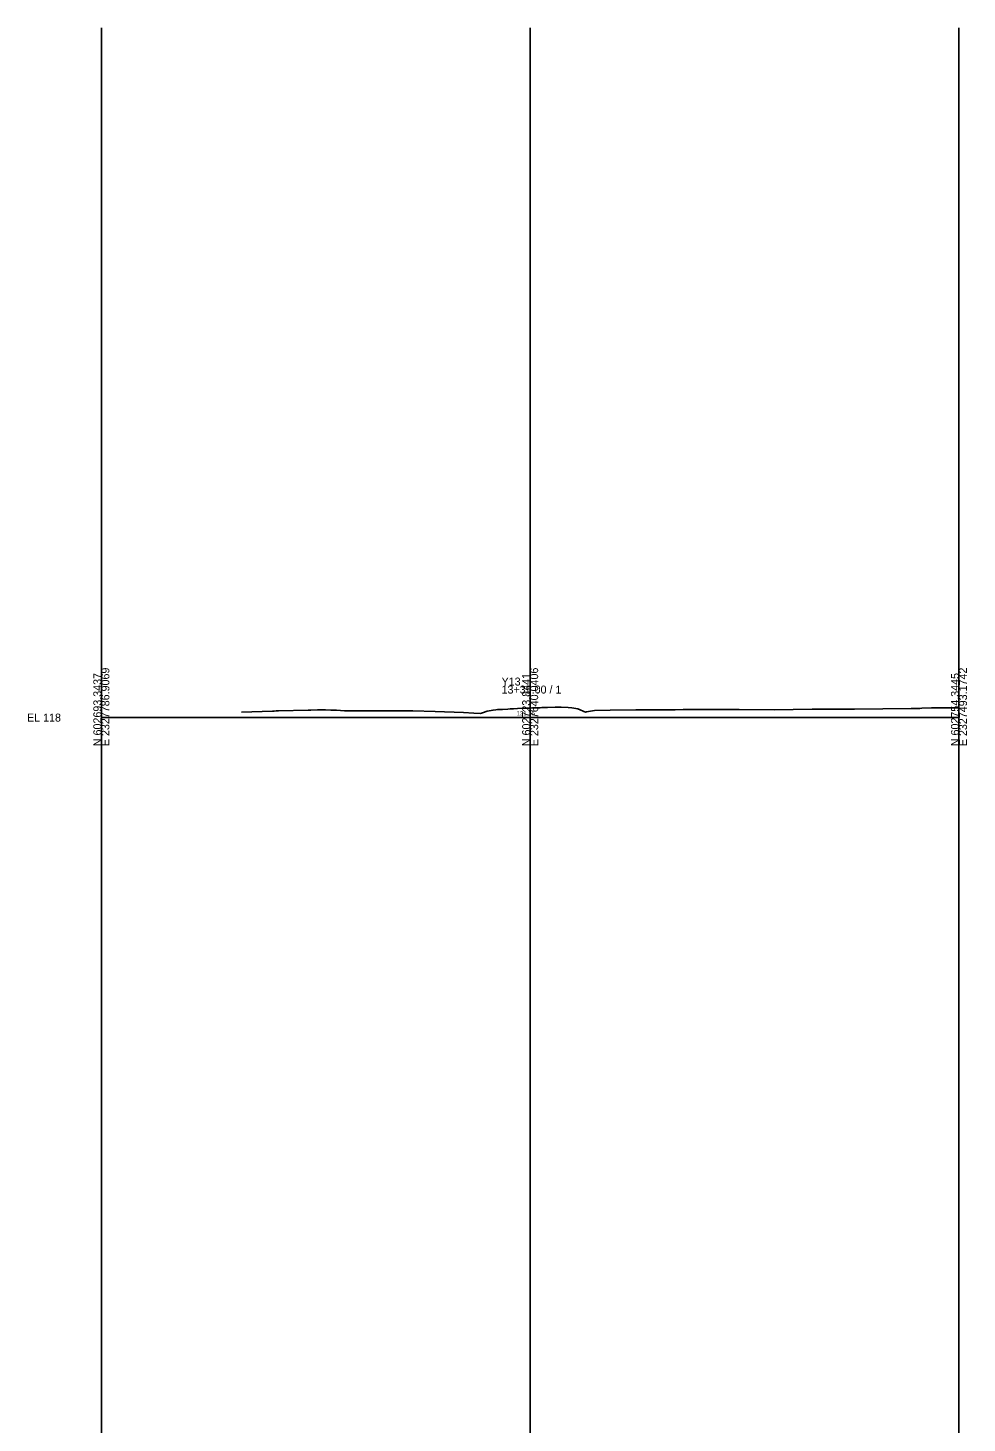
# Model space of a CAD drawing. Extents: x -26 to 1603, y -711 to 1241.
# Drawn here: x -25.7 to 302.8, y 753.1 to 1241.3 of the extents above; entities that cross this region are included whole.
import ezdxf

# ---------------------------------------------------------------- set-up
doc = ezdxf.new("R2010")
doc.units = 0
for name, color, linetype in [('Exist CMT Pavement', 7, 'Continuous'), ('Exist Cross Section Cell', 7, 'Continuous'), ('Exist XS Center Line Elevation Label', 7, 'Continuous'), ('Exist XS Ground Line', 7, 'Continuous'), ('Prop XS Earthwork Shape', 7, 'Continuous'), ('Scratch_Level_9', 7, 'Continuous')]:
    doc.layers.add(name, color=color, linetype=linetype)

msp = doc.modelspace()

# ---------------------------------------------------------------- linework, layer by layer
at = {"layer": 'Exist CMT Pavement'}
for p, q in [((149.9, 1003.45), (149.9, 1003.25)), ((149.9, 1003.45), (150, 1003.45)), ((149.9, 1003.25), (150, 1003.25)), ((150.1, 1003.45), (150, 1003.45)), ((150.1, 1003.25), (150, 1003.25)), ((150.1, 1003.45), (150.1, 1003.25))]:
    msp.add_line(p, q, dxfattribs=at)
at = {"layer": 'Exist Cross Section Cell'}
for p, q in [((150, 1000), (150, 1011.21)), ((0, 1000), (150, 1000)), ((150, 1000), (300, 1000))]:
    msp.add_line(p, q, dxfattribs=at)
at = {"layer": 'Exist XS Ground Line'}
msp.add_lwpolyline([(48.97, 1001.95), (59.88, 1002.28), (60.44, 1002.3), (61.13, 1002.32), (61.95, 1002.35), (72.39, 1002.61), (72.83, 1002.6), (73.33, 1002.63), (75.63, 1002.72), (76.14, 1002.74), (78.38, 1002.73), (80.32, 1002.63), (82.29, 1002.57), (85.1, 1002.36), (89.24, 1002.39), (104.44, 1002.38), (108.95, 1002.34), (116.78, 1002.12), (126.68, 1001.82), (130.24, 1001.58), (132.59, 1001.48), (133.37, 1001.72), (134.93, 1002.24), (137.02, 1002.6), (138.02, 1002.77), (138.57, 1002.78), (140.34, 1002.88), (142.14, 1002.98), (142.96, 1003.02), (144.13, 1003.08), (145.58, 1003.15), (148.24, 1003.28), (149.24, 1003.32), (150.08, 1003.35), (150.83, 1003.37), (152.1, 1003.41), (153.45, 1003.46), (154.09, 1003.48), (156.11, 1003.55), (158.7, 1003.63), (159.04, 1003.64), (160.06, 1003.67), (160.86, 1003.69), (163.31, 1003.59), (164.61, 1003.41), (166.62, 1003.07), (169.4, 1001.92), (169.72, 1001.98), (172.46, 1002.47), (177.96, 1002.58), (186.95, 1002.72), (188.78, 1002.72), (190.95, 1002.73), (193.39, 1002.73), (196.07, 1002.74), (198.15, 1002.74), (200.78, 1002.76), (203.56, 1002.78), (206.41, 1002.8), (207.98, 1002.79), (218.53, 1002.79), (223.11, 1002.78), (235.41, 1002.7), (248.69, 1002.9), (252.8, 1002.96), (261.31, 1002.95), (262.38, 1002.96), (263.48, 1002.99), (283.28, 1003.2), (286.34, 1003.23), (287.06, 1003.25), (290.38, 1003.36), (300, 1003.47)], dxfattribs=at)
at = {"layer": 'Prop XS Earthwork Shape'}
msp.add_lwpolyline([(150.08, 1003.35), (150.1, 1003.35), (150.1, 1003.25), (150, 1003.25), (149.9, 1003.25), (149.9, 1003.34)], close=True, dxfattribs=at)
at = {"layer": 'Scratch_Level_9'}
for p, q in [((0, 1241.32), (0, -711.39)), ((150, 1241.32), (150, -711.39)), ((300, 1241.32), (300, -711.39))]:
    msp.add_line(p, q, dxfattribs=at)

# ---------------------------------------------------------------- texts
at = {"layer": 'Exist Cross Section Cell'}
for s, p in [('N 602693.3437', (0, 990)), ('E 2327786.9069', (2.8, 990)), ('N 602723.8441', (150, 990)), ('E 2327640.0406', (152.8, 990)), ('N 602754.3445', (300, 990)), ('E 2327493.1742', (302.8, 990))]:
    msp.add_text(s, height=2.8, rotation=90, dxfattribs=at).set_placement(p)
for s, p in [('Y13', (140, 1011.21)), ('13+35.00 / 1', (140, 1008.41)), ('EL 118', (-26, 998.6))]:
    msp.add_text(s, height=2.8, dxfattribs=at).set_placement(p)
at = {"layer": 'Exist XS Center Line Elevation Label'}
msp.add_text('121.35', height=1.5, dxfattribs=at).set_placement((145.3, 1000.77))

doc.saveas('drawing.dxf')
